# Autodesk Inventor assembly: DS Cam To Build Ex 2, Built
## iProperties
Created: 2006-07
Part Number: DS Cam To Build Ex 2, Built
Document SubType Name: Assembly
Designer: Maxime Debono
Author: Maxime Debono
